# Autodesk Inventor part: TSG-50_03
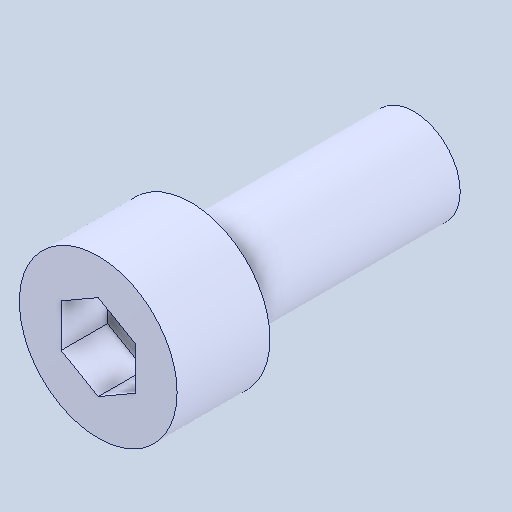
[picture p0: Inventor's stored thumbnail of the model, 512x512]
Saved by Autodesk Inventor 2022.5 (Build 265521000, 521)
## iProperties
Created: 2024-05
Part Number: TSG-50_03
Material: 一般
Document SubType Name: Modeling
Designer: ImaoCorp
Density: 1 g/cm^3
Appearance: 既定
Author: ImaoCorp
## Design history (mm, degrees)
feature "TSG-50_03"
node "ソリッド1"
